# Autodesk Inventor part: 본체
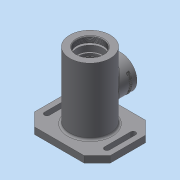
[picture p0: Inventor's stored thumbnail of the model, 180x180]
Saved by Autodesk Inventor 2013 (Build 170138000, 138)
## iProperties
Created: 2017-10
Part Number: 본체
Material: 일반
Document SubType Name: Modeling
Designer: dgall
Density: 1 g/cm^3
Author: dgall
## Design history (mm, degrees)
sketch "스케치1"
  geometry: L1 (-58, 47)-(58, 47); L2 (58, 47)-(58, -47); L3 (58, -47)-(-58, -47); L4 (-58, -47)-(-58, 47); 3 further points
  constraints: 8 end point, 2 midpoint, 2 parallel, 1 horizontal, 1 horizontal alignment, 1 perpendicular, 1 vertical alignment
  dimensions: "d0" = 116 distance of L1.start L1.end; "d2" = 94 distance of L1.end L2.end
extrude "돌출1" new body sketch "스케치1" distance "d3" = 10; taper "d4" = 0 deg
sketch "스케치2"
  geometry: C1 r 31 at (0, 0); 1 further point
  constraints: 1 centre point, 1 coincident
  dimensions: "d5" = 62 diameter of C1
extrude "돌출2" join sketch "스케치2" distance "d7" = 102; taper "d8" = 0 deg
chamfer "모따기1" distance "d9" = 20; stored, may be unused: second distance "d10" = 2, angle "d11" = 45 deg
sketch "스케치3"
  geometry: L1 (-42, -20)-(-42, 20); L2 (-50, -20)-(-50, 20); L3 (50, -20)-(50, 20); L4 (42, -20)-(42, 20); A1 r 4 centre (-46, 20) between (-42, 20) and (-50, 20); A2 r 4 centre (-46, -20) between (-42, -20) and (-50, -20); A3 r 4 centre (46, 20) between (50, 20) and (42, 20); A4 r 4 centre (46, -20) between (50, -20) and (42, -20); 3 further points
  constraints: 8 end point, 8 point on circle, 8 tangent, 4 centre point, 2 equal radius, 2 horizontal alignment, 2 midpoint, 2 vertical alignment
  dimensions: "d12" = 40 distance of A2.centre A1.centre; "d14" = 40 distance of A4.centre A3.centre; "d15" = 8 diameter of A3; "d16" = 8 diameter of A1; "d17" = 46 horizontal distance of A2.centre point (0, 0); "d18" = 46 horizontal distance of point (0, 0) A4.centre
extrude "돌출3" cut sketch "스케치3" distance "d19" = 102; taper "d20" = 0 deg
fillet "모깎기1" dims "d21" = 3
sketch "스케치4"
  geometry: C1 r 35 at (0, 0); 1 further point
  constraints: 1 centre point, 1 coincident
  dimensions: "d22" = 70 diameter of C1
extrude "돌출4" join sketch "스케치4" distance "d24" = 3; taper "d25" = 0 deg
sketch "스케치5"
  geometry: C1 r 31 at (0, 0) reference; 1 further point
  constraints: 1 coincident
hole "구멍1" sketch "스케치5" at (0, 0) diameter "d26" = 40.376; stored, may be unused: countersink angle "d30" = 90 deg, drill point angle "d32" = 0 deg; dims "d27" = 6, "d28" = 4, "d29" = 2, "d31" = 9
node "작업 평면1"
sketch "스케치6"
  geometry: L1 (31, 112)-(-31, 112) reference; L2 (-35, -3)-(35, -3) reference; L3 (0, -3)-(0, 112); L4 (20.188, 103)-(-20.188, 103) reference; L5 (20.188, 103)-(20.188, 112) reference; L6 (20.188, 103)-(24, 103); L7 (24, 103)-(24, 100); L8 (24, 100)-(20, 100); L9 (20, 100)-(20, 91); L10 (20, 91)-(17.5, 91); L11 (17.5, 91)-(17.5, 87.75); L12 (17.5, 87.75)-(18.5, 87.75); L13 (18.5, 87.75)-(18.5, 86); L14 (18.5, 86)-(17.5, 86); L15 (17.5, 86)-(17.5, 75); L16 (17.5, 75)-(26, 75); L17 (26, 75)-(26, 37); L18 (26, 37)-(17.5, 37); L19 (17.5, 37)-(17.5, 26); L20 (17.5, 26)-(16.5, 26); L21 (16.5, 26)-(16.5, 21); L22 (16.5, 21)-(10, 21); L23 (10, 21)-(10, 18.3); L24 (10, 18.3)-(12.5, 18.3); L25 (12.5, 18.3)-(12.5, 11); L26 (12.5, 11)-(16, 11); L27 (16, 11)-(22, -3); 1 further point
  constraints: 46 end point, 19 parallel, 2 midpoint, 2 perpendicular, 1 point on line
  dimensions: "d34" = 3 distance of L6.end L7.end; "d36" = 9 distance of L8.end L9.end; "d37" = 1.75 distance of L12.end L13.end; "d38" = 48 diameter of L7 L3; "d39" = 40 diameter of L9 L3; "d40" = 35 diameter of L11 L3; "d41" = 37 diameter of L13 L3; "d42" = 35 diameter of L15 L3; "d43" = 52 diameter of L17 L3; "d44" = 38 distance of L16.end L17.end; "d45" = 26 vertical distance of L1.start L13.end; "d46" = 11 distance of L14.end L15.end; "d47" = 35 diameter of L19 L3; "d48" = 33 diameter of L21 L3; "d49" = 11 distance of L18.end L19.end; "d50" = 2.7 distance of L22.end L23.end; "d51" = 7.3 distance of L24.end L25.end; "d52" = 14 distance from line of L2 L26.end; "d53" = 44 diameter of L27.end L3; "d54" = 32 diameter of L26.end L3; "d55" = 20 diameter of L23 L3; "d56" = 25 diameter of L25 L3
revolve "회전1" sketch "스케치6" stored, may be unused: angle "d57" = 90 deg
fillet "모깎기2" dims "d58" = 3
fillet "모깎기3" dims "d59" = 3
fillet "모깎기4" dims "d63" = 3
chamfer "모따기3" distance "d64" = 1; stored, may be unused: second distance "d65" = 2, angle "d66" = 30 deg
node "작업 평면2"
sketch "스케치7"
  geometry: L1 (38, 0)-(-38, 0) reference; L2 (31, 112)-(-31, 112) reference; C1 r 25 at (0, 56); 2 further points
  constraints: 1 centre point, 1 midpoint, 1 vertical alignment
  dimensions: "d68" = 56 distance from line of L2 C1.centre; "d69" = 50 diameter of C1
extrude "돌출5" join sketch "스케치7" stored distance "d70" = 3; taper "d71" = 0 deg
fillet "모깎기5" dims "d72" = 3
sketch "스케치8"
  geometry: C1 r 25 at (0, 0) reference; C2 r 16 at (0, 0); 1 further point
  constraints: 1 centre point, 1 coincident
  dimensions: "d73" = 32 diameter of C2
extrude "돌출6" cut sketch "스케치8" stored distance "d75" = 3; taper "d76" = 0 deg
chamfer "모따기4" distance "d88" = 1; stored, may be unused: second distance "d89" = 2, angle "d90" = 30 deg
node "작업 평면3"
sketch "스케치10"
  geometry: L1 (-7.598, 16.346)-(-7.598, -16.346); L2 (-7.598, -16.346)-(-12.402, -16.346); L3 (-12.402, -16.346)-(-12.402, 16.346); L4 (-12.402, 16.346)-(-7.598, 16.346); L5 (-16, 56)-(-78, 56) reference; L6 (0, 25)-(0, -25) reference; 3 further points
  constraints: 2 midpoint, 2 other
  dimensions: "d91" = 56 distance from line of L5 point (-7.598, 0); "d92" = 10 distance from line of L6 point (-10, -16.346)
feature "엠보싱1" sketch "스케치10" dims "d0" = 116, "d2" = 94, "d93" = 0.5, "d94" = 0
sketch "스케치11"
  geometry: C1 r 25 at (0, 0) reference; 2 further points
  constraints: 1 horizontal alignment
  dimensions: "d95" = 20.5 distance of C1.centre point (-20.5, 0)
hole "구멍3" sketch "스케치11" at (-20.5, 0) diameter "d96" = 2.459; stored, may be unused: countersink angle "d100" = 90 deg, drill point angle "d102" = 118 deg; dims "d97" = 6, "d98" = 4, "d99" = 2, "d101" = 8
chamfer "모따기5" distance "d106" = 0.7; stored, may be unused: second distance "d107" = 2, angle "d108" = 30 deg
fillet "모깎기6" dims "d109" = 0.3
chamfer "모따기6" distance "d110" = 1; stored, may be unused: second distance "d111" = 2, angle "d112" = 30 deg
fillet "모깎기7" dims "d113" = 0.3
node "솔리드1"
pattern_circular "원형 패턴2" dims angle "d104" = 360 deg
other parameters: "d33" = 0, "d67" = 47
